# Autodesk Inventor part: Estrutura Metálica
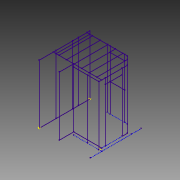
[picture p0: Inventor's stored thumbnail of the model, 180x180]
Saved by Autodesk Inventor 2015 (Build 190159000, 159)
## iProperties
Created: 2015-04
Part Number: Estrutura Metálica
Material: Generic
Document SubType Name: Modeling
Designer: suporte
Density: 1 g/cm^3
Appearance: Default
Author: suporte
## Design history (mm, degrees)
sketch "3D Sketch1" dims "d0" = 2100, "d1" = 2100, "d7" = 2100, "d8" = 100, "d9" = 100, "d10" = 2100, "d14" = 900, "d15" = 230, "d16" = 600, "d17" = 2100, "d18" = 400, "d19" = 900, "d20" = 200, "d21" = 200, "d23" = 1000, "d24" = 2100 (derived), "d25" = 2100, "d26" = 600, "d28" = 400, "d29" = 210, "d30" = 500 (derived), "d31" = 100, "d32" = 100, "d33" = 270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
  workpoint "Work Point1"
  workpoint "Work Point2"
  workpoint "Work Point3"
